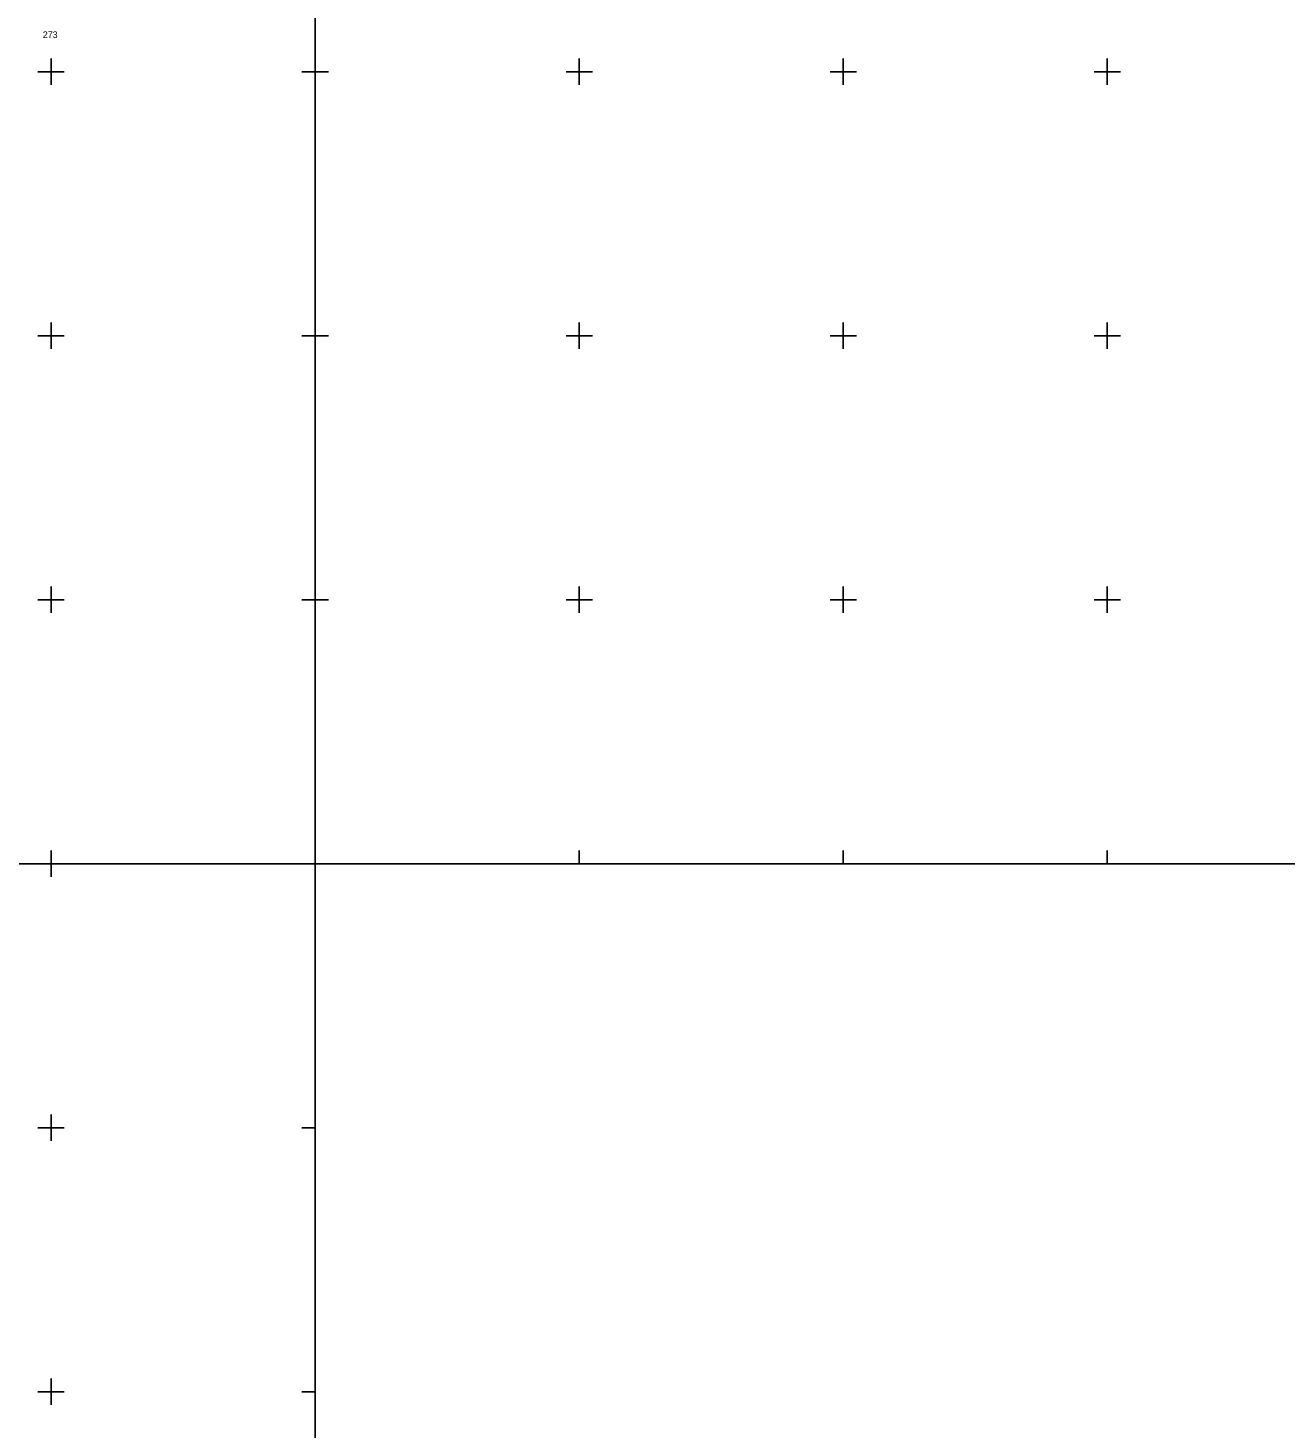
# Model space of a CAD drawing. Extents: x 4632591 to 4653165, y 5351032 to 5369868.
# Drawn here: x 4647545.6 to 4647783.8, y 5363393.1 to 5363658.3 of the extents above; entities that cross this region are included whole.
import ezdxf

# ---------------------------------------------------------------- set-up
doc = ezdxf.new("R2010")
doc.units = 0
doc.layers.add('EDZPD_211', color=7, linetype='Continuous')
doc.layers.add('Warstwa 60', color=7, linetype='Continuous')

msp = doc.modelspace()

# ---------------------------------------------------------------- linework, layer by layer
at = {"layer": 'Warstwa 60'}
for p, q in [((4647550, 5363647.5), (4647550, 5363652.5)), ((4647650, 5363647.5), (4647650, 5363652.5)), ((4647700, 5363647.5), (4647700, 5363652.5)), ((4647750, 5363647.5), (4647750, 5363652.5)), ((4647547.5, 5363650), (4647552.5, 5363650)), ((4647597.5, 5363650), (4647600, 5363650)), ((4647600, 5363650), (4647602.5, 5363650)), ((4647647.5, 5363650), (4647652.5, 5363650)), ((4647697.5, 5363650), (4647702.5, 5363650)), ((4647747.5, 5363650), (4647752.5, 5363650)), ((4647550, 5363597.5), (4647550, 5363602.5)), ((4647650, 5363597.5), (4647650, 5363602.5)), ((4647700, 5363597.5), (4647700, 5363602.5)), ((4647750, 5363597.5), (4647750, 5363602.5)), ((4647547.5, 5363600), (4647552.5, 5363600)), ((4647597.5, 5363600), (4647600, 5363600)), ((4647600, 5363600), (4647602.5, 5363600)), ((4647647.5, 5363600), (4647652.5, 5363600)), ((4647697.5, 5363600), (4647702.5, 5363600)), ((4647747.5, 5363600), (4647752.5, 5363600)), ((4647550, 5363547.5), (4647550, 5363552.5)), ((4647650, 5363547.5), (4647650, 5363552.5)), ((4647700, 5363547.5), (4647700, 5363552.5)), ((4647750, 5363547.5), (4647750, 5363552.5)), ((4647547.5, 5363550), (4647552.5, 5363550)), ((4647597.5, 5363550), (4647600, 5363550)), ((4647600, 5363550), (4647602.5, 5363550)), ((4647647.5, 5363550), (4647652.5, 5363550)), ((4647697.5, 5363550), (4647702.5, 5363550)), ((4647747.5, 5363550), (4647752.5, 5363550)), ((4647550, 5363500), (4647550, 5363502.5)), ((4647650, 5363500), (4647650, 5363502.5)), ((4647700, 5363500), (4647700, 5363502.5)), ((4647750, 5363500), (4647750, 5363502.5)), ((4647550, 5363497.5), (4647550, 5363500)), ((4647547.5, 5363450), (4647552.5, 5363450)), ((4647550, 5363447.5), (4647550, 5363452.5)), ((4647597.5, 5363450), (4647600, 5363450)), ((4647550, 5363397.5), (4647550, 5363402.5)), ((4647547.5, 5363400), (4647552.5, 5363400)), ((4647597.5, 5363400), (4647600, 5363400))]:
    msp.add_line(p, q, dxfattribs=at)
for points in [[(4647200, 5363500), (4647200, 5363750), (4647600, 5363750), (4647600, 5363500)], [(4647600, 5363500), (4647600, 5363750), (4648000, 5363750), (4648000, 5363500)], [(4647200, 5363250), (4647200, 5363500), (4647600, 5363500), (4647600, 5363250)]]:
    msp.add_lwpolyline(points, close=True, dxfattribs=at)

# ---------------------------------------------------------------- texts
at = {"layer": 'EDZPD_211'}
msp.add_text('273', height=1.25, dxfattribs=at).set_placement((4647548.44, 5363656.38))

doc.saveas('drawing.dxf')
